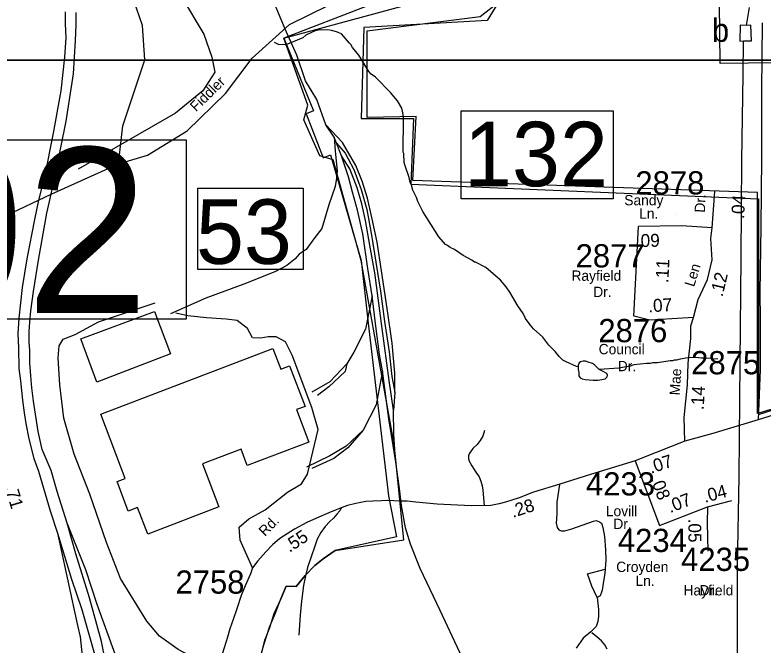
# Model space of a CAD drawing. Extents: x 1551653 to 1702041, y 811336 to 920032.
# Drawn here: x 1634040 to 1638801, y 827587 to 831594 of the extents above; entities that cross this region are included whole.
import ezdxf

# ---------------------------------------------------------------- set-up
doc = ezdxf.new("R2010")
doc.units = 0
for name, color, linetype in [('Old_Level_11', 7, 'Continuous'), ('Old_Level_17', 7, 'Continuous'), ('Old_Level_21', 7, 'Continuous'), ('Old_Level_22', 7, 'Continuous'), ('Old_Level_28', 7, 'Continuous'), ('Old_Level_31', 7, 'Continuous'), ('Old_Level_32', 7, 'Continuous'), ('Old_Level_35', 7, 'Continuous'), ('Old_Level_4', 7, 'Continuous'), ('Old_Level_41', 7, 'Continuous'), ('Old_Level_44', 7, 'Continuous'), ('Old_Level_47', 7, 'Continuous'), ('Old_Level_48', 7, 'Continuous'), ('Old_Level_49', 7, 'Continuous'), ('Old_Level_50', 7, 'Continuous'), ('Old_Level_56', 7, 'Continuous'), ('Old_Level_59', 7, 'Continuous'), ('Old_Level_62', 7, 'Continuous'), ('Old_Level_63', 7, 'Continuous'), ('Old_Level_8', 7, 'Continuous')]:
    doc.layers.add(name, color=color, linetype=linetype)

msp = doc.modelspace()

# ---------------------------------------------------------------- linework, layer by layer
at = {"layer": 'Old_Level_11'}
msp.add_line((1638247.283, 830327.148), (1638247.283, 830327.148), dxfattribs=at)
at = {"layer": 'Old_Level_28'}
for points in [[(1634358.924, 831613.638), (1634358.924, 831537.56), (1634362.23, 831448.913), (1634355.618, 831326.526), (1634332.478, 831111.522), (1634282.892, 830843.596), (1634226.694, 830565.745), (1634189.157, 830416.652)], [(1634270.63, 830455.02), (1634299.421, 830595.515), (1634365.535, 830919.673), (1634411.816, 831220.678), (1634425.039, 831431.712), (1634428.344, 831530.944), (1634428.344, 831610.33)], [(1634371.026, 828362.934), (1634308.827, 828564.219), (1634269.435, 828697.027), (1634213.472, 828829.841), (1634187.026, 828945.611), (1634173.802, 829028.306), (1634157.274, 829137.46), (1634147.356, 829223.463), (1634140.745, 829299.54), (1634134.134, 829382.234), (1634134.134, 829461.62), (1634130.828, 829511.236), (1634130.828, 829580.699), (1634134.134, 829640.238), (1634140.745, 829713.009), (1634157.274, 829835.395), (1634190.331, 830033.86), (1634243.223, 830334.203), (1634270.63, 830455.02)], [(1634189.157, 830416.652), (1634163.885, 830294.51), (1634114.3, 830043.783), (1634084.547, 829861.857), (1634074.63, 829762.625), (1634064.713, 829666.7), (1634058.101, 829567.468), (1634061.408, 829478.159), (1634064.713, 829345.849), (1634074.63, 829266.464), (1634087.854, 829144.077), (1634097.771, 829064.691), (1634107.688, 828995.228), (1634127.522, 828899.304), (1634160.58, 828773.61), (1634188.576, 828692.876), (1634263.214, 828439.713), (1634310.845, 828297.386)], [(1634706.713, 826688.852), (1634694.274, 826919.189), (1634679.155, 827039.961), (1634668.53, 827132.105), (1634667.321, 827172.353), (1634659.028, 827242.906), (1634646.588, 827325.911), (1634590.74, 827608.448), (1634514.028, 827886.513), (1634426.59, 828167.654), (1634371.026, 828362.934)], [(1634310.845, 828297.386), (1634400.052, 828006.014), (1634464.324, 827813.028), (1634549.274, 827512.993), (1634590.608, 827263.658), (1634591.389, 827220.176), (1634605.557, 827128.032), (1634626.315, 826932.859), (1634628.565, 826826.957), (1634634.148, 826751.105)]]:
    msp.add_lwpolyline(points, dxfattribs=at)
at = {"layer": 'Old_Level_31'}
for p, q in [((1634270.63, 830455.02), (1634270.63, 830455.02)), ((1634189.157, 830416.652), (1634189.157, 830416.652)), ((1636513.137, 828501.068), (1636513.137, 828501.068))]:
    msp.add_line(p, q, dxfattribs=at)
for points in [[(1636878.657, 830984.868), (1637847.179, 830984.868), (1637847.179, 830424.869), (1636878.657, 830424.869), (1636878.657, 830984.868)], [(1635202.761, 830493.353), (1635872.772, 830493.353), (1635872.772, 829975.07), (1635202.761, 829975.07), (1635202.761, 830493.353)]]:
    msp.add_lwpolyline(points, dxfattribs=at)
at = {"layer": 'Old_Level_32'}
for p, q in [((1638475.955, 830239.921), (1638492.8, 830471.752)), ((1637978.998, 829679.311), (1638008.478, 830248.351)), ((1637986.236, 828758.346), (1638141.372, 828347.597)), ((1638447.16, 828465.178), (1638601.884, 828506.66)), ((1638141.372, 828347.597), (1638447.16, 828465.178))]:
    msp.add_line(p, q, dxfattribs=at)
for points in [[(1638475.955, 830239.921), (1638282.226, 830252.566), (1638008.478, 830248.351)], [(1638358.033, 829670.881), (1638387.514, 829784.689), (1638446.474, 829911.142), (1638475.955, 830037.595), (1638467.531, 830172.479), (1638475.955, 830239.921)], [(1638358.033, 829670.881), (1638219.053, 829662.45), (1638080.074, 829654.02), (1637978.998, 829679.311)], [(1638303.283, 828882.655), (1638299.072, 829034.399), (1638320.129, 829240.94), (1638324.341, 829380.038), (1638341.187, 829535.997), (1638341.187, 829616.084), (1638358.033, 829670.881)], [(1639243.267, 829151.164), (1639189.106, 829142.423), (1639129.704, 829131.933), (1638770.493, 829020.049), (1638481.315, 828932.521), (1638303.283, 828882.655)], [(1638303.283, 828882.655), (1638119.613, 828810.373), (1637986.236, 828758.346)], [(1637986.236, 828758.346), (1637701.396, 828672.39), (1637506.982, 828609.054), (1637340.407, 828558.955), (1637247.5, 828523.201), (1637200.827, 828508.546), (1637162.338, 828496.442), (1637120.647, 828483.87), (1637068.833, 828474.931), (1636943.766, 828473.143), (1636727.579, 828482.082), (1636590.006, 828496.384), (1636535.101, 828500.83), (1636498.022, 828500.83), (1636491.172, 828501.308)], [(1636491.172, 828501.308), (1636409.443, 828507.014), (1636372.363, 828504.953), (1636316.744, 828502.891), (1636273.486, 828498.768), (1636209.627, 828486.401), (1636156.067, 828474.034), (1636114.868, 828459.606), (1636083.968, 828447.238), (1636036.589, 828426.626), (1635958.311, 828393.646), (1635896.511, 828366.851), (1635818.233, 828323.565), (1635772.913, 828294.709), (1635725.534, 828263.79), (1635678.155, 828224.627), (1635636.956, 828179.28), (1635584.185, 828121.586), (1635551.485, 828078.226), (1635538.802, 828039.177), (1635504.103, 827963.625), (1635478.322, 827902.246), (1635450.57, 827817.808), (1635427.675, 827749.83), (1635408.019, 827689.926), (1635393.105, 827637.5), (1635360.983, 827535.091)], [(1638447.16, 828465.178), (1638444.847, 828361.169), (1638446.104, 828275.299), (1638448.636, 828183.196)]]:
    msp.add_lwpolyline(points, dxfattribs=at)
at = {"layer": 'Old_Level_35'}
for points in [[(1635099.918, 831711.725), (1635241.901, 831471.781), (1635291.453, 831326.319), (1635311.275, 831230.447), (1635235.293, 831111.432), (1635060.364, 830970.191), (1634442.599, 830613.147)], [(1638794.954, 831543.394), (1638791.46, 831116.835), (1638789.713, 830685.03), (1638786.218, 830248.331), (1638780.977, 829832.261), (1638782.724, 829654.643), (1638782.724, 829339.968), (1638770.493, 829020.049)], [(1635328.24, 827429.008), (1635222.737, 827481.324), (1635077.381, 827557.361), (1634958.453, 827643.316), (1634879.168, 827739.188), (1634710.686, 828010.277), (1634621.49, 828238.387), (1634515.776, 828545.842), (1634416.669, 828800.4), (1634350.635, 829030.78), (1634324.207, 829242.361), (1634314.297, 829414.271), (1634320.903, 829490.308), (1634347.332, 829533.286), (1634423.314, 829563.039), (1634571.773, 829641.668), (1634931.861, 829763.988)], [(1635551.485, 828078.226), (1635472.731, 828254.063), (1635466.123, 828336.712), (1635528.892, 828389.608), (1635631.301, 828445.809), (1635773.355, 828558.211), (1635862.551, 828611.107), (1635902.193, 828673.92), (1635935.228, 828816.076), (1635968.264, 828958.232), (1635928.622, 829097.082), (1635803.086, 829430.984), (1635760.336, 829515.06), (1635700.872, 829548.119), (1635651.319, 829548.119), (1635605.069, 829538.201), (1635552.212, 829541.507), (1635519.177, 829601.014), (1635453.106, 829650.604), (1635383.731, 829660.522), (1635258.196, 829667.134), (1635139.268, 829680.357), (1635063.286, 829696.887)], [(1637027.894, 828952.057), (1637017.36, 828916.049), (1637000.788, 828888.372), (1636980.457, 828862.772), (1636954.122, 828837.093), (1636937.671, 828815.413), (1636929.627, 828803.573), (1636925.342, 828789.652), (1636927.058, 828775.61), (1636928.935, 828759.563), (1636946.287, 828727.191), (1636973.682, 828686.814), (1636993.078, 828656.604), (1637004.709, 828628.353), (1637012.343, 828600.184), (1637017.773, 828572.057), (1637025.597, 828474.313)], [(1637504.919, 828608.382), (1637487.274, 828495.385), (1637487.274, 828419.51), (1637483.827, 828360.879), (1637490.721, 828333.289), (1637501.061, 828319.493), (1637514.848, 828312.595), (1637538.976, 828312.595), (1637583.784, 828326.391), (1637721.655, 828374.675), (1637738.889, 828378.124), (1637759.569, 828371.226), (1637773.357, 828360.879), (1637780.25, 828333.289), (1637790.591, 828278.107), (1637797.484, 828191.885), (1637800.931, 828126.356), (1637794.038, 828043.583), (1637783.698, 827978.055), (1637776.804, 827936.668), (1637769.91, 827915.975), (1637763.017, 827898.731), (1637745.783, 827888.384)], [(1636114.868, 828459.606), (1636106.628, 828440.643), (1636088.088, 828420.031), (1636067.489, 828393.235), (1636042.992, 828371.743), (1636014.537, 828340.302), (1635986.768, 828303.045), (1635963.261, 828259.099), (1635948.563, 828215.175), (1635902.395, 828080.041), (1635889.494, 828026.271), (1635876.433, 827964.506), (1635864.009, 827865.103), (1635855.413, 827776.829), (1635845.41, 827648.965)], [(1637745.783, 827888.384), (1637711.315, 827960.81), (1637683.74, 828040.134), (1637796.251, 828070.155)], [(1637745.783, 827888.384), (1637752.676, 827812.509), (1637752.676, 827767.674), (1637749.229, 827736.634), (1637738.889, 827705.594), (1637704.421, 827671.105)], [(1637704.421, 827671.105), (1637656.167, 827629.719), (1637611.358, 827567.639)], [(1637807.825, 827560.741), (1637794.038, 827588.332), (1637773.357, 827612.474), (1637745.783, 827636.617), (1637711.315, 827664.208)]]:
    msp.add_lwpolyline(points, dxfattribs=at)
at = {"layer": 'Old_Level_4'}
msp.add_lwpolyline([(1631997.722, 830799.374), (1635129.916, 830799.374), (1635129.916, 829659.611), (1631997.722, 829659.611), (1631997.722, 830799.374)], dxfattribs=at)
at = {"layer": 'Old_Level_41'}
for points in [[(1634458.377, 829534.774), (1634926.552, 829707.698), (1635029.662, 829439.944), (1634561.487, 829258.654), (1634458.377, 829534.774)], [(1634586.013, 829054.492), (1635681.683, 829472.486), (1635731.741, 829341.274), (1635787.518, 829362.554), (1635885.908, 829104.657), (1635832.111, 829084.133), (1635910.844, 828877.762), (1635518.277, 828727.994), (1635478.176, 828833.105), (1635233.224, 828739.652), (1635337.834, 828465.459), (1634884.451, 828292.485), (1634820.321, 828460.577), (1634761.039, 828437.96), (1634688.925, 828626.977), (1634741.472, 828647.024), (1634586.013, 829054.492)]]:
    msp.add_lwpolyline(points, dxfattribs=at)
at = {"layer": 'Old_Level_44'}
for p, q in [((1636071.64, 830816.272), (1636017.228, 830895.735)), ((1636085.311, 830779.976), (1636071.64, 830816.272)), ((1636118.093, 830699.468), (1636085.311, 830779.976)), ((1636456.685, 829192.984), (1636449.208, 829081.075))]:
    msp.add_line(p, q, dxfattribs=at)
for points in [[(1636017.228, 830895.735), (1635961.26, 831056.358), (1635889.071, 831175.905), (1635832.911, 831337.897), (1635758.747, 831504.428), (1635669.669, 831719.552), (1635631.472, 831855.401), (1635602.436, 831936.501), (1635589.457, 832016.606), (1635575.311, 832139.713), (1635578.614, 832275.257), (1635596.03, 832374.566), (1635619.105, 832466.347), (1635652.671, 832581.928), (1635710.043, 832697.226), (1635775.249, 832794.352), (1635934.068, 832983.007)], [(1636456.685, 829192.984), (1636458.165, 829315.018), (1636440.658, 829507.278), (1636407.515, 829727.668), (1636372.538, 829966.106), (1636345.028, 830148.563), (1636311.026, 830306.939), (1636282.496, 830429.383), (1636250.084, 830537.9), (1636209.671, 830636.774), (1636123.205, 830783.608), (1636017.228, 830895.735)], [(1636071.64, 830816.272), (1636076.495, 830730.127), (1636090.902, 830601.968), (1636086.961, 830555.823), (1636077.703, 830503.983), (1636038.097, 830386.522), (1635991.585, 830235.758), (1635940.833, 830169.821), (1635892.478, 830103.52), (1635848.309, 830072.082), (1635823.104, 830044.012), (1635770.247, 830001.035), (1635694.265, 829961.364), (1635496.052, 829882.021), (1635254.893, 829792.76), (1635030.251, 829693.581)], [(1636085.311, 830779.976), (1636140.426, 830715.222), (1636196.541, 830611.026), (1636243.385, 830484.009), (1636279.635, 830357.405), (1636309.513, 830193.107), (1636337.269, 830022.655), (1636366.938, 829838.151), (1636390.406, 829643.971), (1636421.915, 829451.429), (1636437.951, 829295.219), (1636456.685, 829192.984)], [(1636449.208, 829081.075), (1636421.616, 829269.336), (1636375.908, 829600.041), (1636330.484, 829954.755), (1636298.851, 830131.093), (1636270.813, 830287.546), (1636246.157, 830393.904), (1636217.381, 830494.34), (1636169.842, 830616.771), (1636118.093, 830699.468)], [(1636312.512, 829808.843), (1636284.799, 829981.297), (1636253.657, 830201.647), (1636219.697, 830352.218), (1636187.201, 830466.538), (1636162.384, 830564.894), (1636118.093, 830699.468)], [(1636312.512, 829808.843), (1636269.991, 829596.504), (1636195.167, 829448.77), (1636150.678, 829375.915)], [(1636379.138, 829330.288), (1636359.733, 829434.28), (1636336.183, 829614.657), (1636312.512, 829808.843)], [(1636150.678, 829375.915), (1636043.499, 829260.561), (1635928.231, 829195.8)], [(1636150.678, 829375.915), (1636140.567, 829327.344), (1636037.432, 829228.18), (1635964.632, 829173.539)], [(1636379.138, 829330.288), (1636338.693, 829113.747), (1636255.781, 828953.87)], [(1636460.996, 828764.865), (1636418.463, 829025.468), (1636379.138, 829330.288)], [(1636460.996, 828764.865), (1636451.121, 828928.953), (1636449.208, 829081.075)], [(1636255.781, 828953.87), (1636146.58, 828852.683), (1636043.445, 828789.946), (1635895.822, 828717.091)], [(1636255.781, 828953.87), (1636158.713, 828840.539), (1636069.734, 828773.756), (1635928.178, 828708.996)], [(1638019.989, 825168.081), (1637879.802, 825458.084), (1637690.957, 825864.536), (1637538.927, 826162.584), (1637443.563, 826363.827), (1637373.465, 826498.722), (1637200.05, 826857.034), (1637087.048, 827086.453), (1636991.763, 827291.699), (1636871.126, 827539.28), (1636744.696, 827806.99), (1636618.023, 828072.705), (1636556.134, 828227.445), (1636525.438, 828331.923), (1636499.316, 828474.331), (1636486.705, 828582.444), (1636460.996, 828764.865)]]:
    msp.add_lwpolyline(points, dxfattribs=at)
at = {"layer": 'Old_Level_47'}
for points in [[(1634914.952, 826501.495), (1634927.338, 826559.336), (1634936.85, 826651.499), (1634932.07, 826716.054), (1634928.579, 826785.921), (1634924.409, 826821.659), (1634903.676, 826908.813), (1634847.698, 827047.846), (1634737.813, 827359.113), (1634561.769, 827844.155), (1634491.277, 828064.117), (1634371.026, 828362.934)], [(1634310.845, 828297.386), (1634419.707, 827790.468), (1634439.453, 827702.969), (1634453.557, 827638.052), (1634462.019, 827559.02), (1634470.482, 827477.168), (1634467.662, 827375.557), (1634456.378, 827268.301), (1634442.274, 827189.27), (1634428.17, 827121.529), (1634405.604, 827048.144), (1634385.858, 826977.581)]]:
    msp.add_lwpolyline(points, dxfattribs=at)
at = {"layer": 'Old_Level_48'}
for points in [[(1635588.429, 827466.777), (1635624.173, 827587.636), (1635660.185, 827700.934), (1635699.992, 827794.925), (1635731.391, 827881.366), (1635766.043, 827961.803), (1635828.768, 827959.655), (1635885.625, 828028.536), (1635947.781, 828091.893), (1636001.521, 828135.78), (1636078.128, 828188.649), (1636513.644, 828256.76), (1636458.499, 828805.521), (1636452.633, 828865.255), (1636243.871, 830033.203), (1636065.099, 830672.246), (1635979.97, 830697.808), (1635877.815, 830927.863), (1635903.354, 831021.59), (1635750.121, 831447.618), (1636941.932, 831771.4)], [(1637112.191, 831669.153), (1637044.088, 831558.386), (1636260.897, 831515.783), (1636243.871, 830936.384), (1636575.876, 830936.384), (1636558.85, 830518.876)], [(1638522.965, 831669.337), (1638883.439, 831673.788), (1638887.89, 831290.974), (1638527.416, 831286.523), (1638522.965, 831669.337)], [(1636558.85, 830518.876), (1638772.213, 830425.149), (1638772.213, 829053.337), (1639087.192, 829155.584)]]:
    msp.add_lwpolyline(points, dxfattribs=at)
at = {"layer": 'Old_Level_49'}
for points in [[(1636572.248, 830542.241), (1636592.241, 830949.27), (1636280.254, 830942.503), (1636280.767, 831493.683), (1637000.089, 831585.136), (1637125.171, 831682.638)], [(1636279.536, 831651.06), (1635750.121, 831447.618), (1635940.483, 830984.128), (1635893.833, 830966.186), (1636000.973, 830685.932), (1636047.725, 830703.874), (1636243.871, 830033.203), (1636288.483, 829633.23), (1636416.511, 828536.012), (1636467.467, 828274.263), (1636078.128, 828188.649), (1636001.521, 828135.78), (1635947.781, 828091.893), (1635885.625, 828028.536), (1635828.768, 827959.655), (1635766.043, 827961.803), (1635731.391, 827881.366), (1635687.126, 827784.13), (1635659.528, 827695.846), (1635628.01, 827615.588), (1635588.429, 827466.777)], [(1639087.192, 829155.584), (1638764.973, 829060.33), (1638764.255, 830464.476), (1636572.248, 830542.241)]]:
    msp.add_lwpolyline(points, dxfattribs=at)
at = {"layer": 'Old_Level_50'}
for p, q in [((1634216.657, 830423.245), (1634216.657, 830423.245)), ((1636489.498, 828504.21), (1636489.498, 828504.21))]:
    msp.add_line(p, q, dxfattribs=at)
at = {"layer": 'Old_Level_56'}
msp.add_line((1638695.86, 831526.973), (1638715.417, 831642.638), dxfattribs=at)
for points in [[(1638695.86, 831526.973), (1638655.887, 831529.387), (1638652.616, 831427.396), (1638676.661, 831429.109)], [(1638676.661, 831429.109), (1638726.716, 831430.493), (1638723.908, 831528.603), (1638695.86, 831526.973)], [(1638613.416, 825833.588), (1638616.369, 826067.656), (1638618.396, 826689.548), (1638637.999, 827457.361), (1638638.072, 828081.497), (1638649.41, 828659.377), (1638654.512, 829383.263), (1638661.037, 830049.285), (1638665.03, 830669.34), (1638673.879, 831213.249), (1638676.661, 831429.109)]]:
    msp.add_lwpolyline(points, dxfattribs=at)
at = {"layer": 'Old_Level_59'}
for points in [[(1634698.892, 830646.972), (1634883.849, 830702.284), (1635134.833, 830858.021), (1635379.87, 831095.984), (1635549.858, 831319.081), (1635785.873, 831534.181), (1636036.857, 831657.109), (1636605.877, 831799.826), (1637731.92, 831911.579), (1639236.9, 832284.774), (1639446.976, 832365.821), (1639875.945, 832728.096), (1639977.958, 832883.578)], [(1634698.892, 830646.972), (1634726.882, 830889.292), (1634865.907, 831309.956), (1634851.861, 831526.85), (1634754.872, 831804.593), (1634735.904, 832320.35), (1634687.922, 832488.698)], [(1631311.239, 828442.267), (1631358.677, 828491.465), (1632279.79, 829058.074), (1632607.874, 829346.839), (1633204.883, 829797.492), (1633936.816, 830298.076), (1634189.157, 830416.652), (1634270.63, 830455.02), (1634698.892, 830646.972)]]:
    msp.add_lwpolyline(points, dxfattribs=at)
at = {"layer": 'Old_Level_62'}
for points in [[(1637624.268, 829357.04), (1637614.22, 829358.988), (1637548.501, 829387.49), (1637526.663, 829399.691), (1637502.775, 829421.837), (1637477.04, 829454.03), (1637437.363, 829494.322), (1637399.838, 829544.612), (1637340.271, 829599.053), (1637318.433, 829623.198), (1637288.7, 829663.388), (1637273.014, 829695.479), (1637239.385, 829743.717), (1637189.968, 829832.043), (1637166.284, 829866.236), (1637130.605, 829908.477), (1637035.256, 829989.216), (1636971.587, 830021.666), (1636963.59, 830021.768), (1636947.699, 830033.866), (1636891.924, 830064.316), (1636836.253, 830102.712), (1636808.366, 830114.913), (1636792.474, 830129.061), (1636780.581, 830135.11), (1636736.905, 830183.452), (1636636.224, 830344.161), (1636602.698, 830408.342), (1636594.804, 830432.436), (1636571.223, 830480.572), (1636563.431, 830512.611), (1636555.536, 830528.657), (1636547.744, 830560.696), (1636520.37, 830640.871), (1636516.474, 830656.865), (1636514.936, 830712.844), (1636510.938, 830720.893), (1636512.475, 830936.711), (1636510.63, 830960.702), (1636500.89, 831000.738), (1636473.311, 831048.925), (1636429.737, 831101.265), (1636334.49, 831197.947), (1636306.603, 831218.144), (1636290.814, 831234.241), (1636227.556, 831338.715), (1636187.981, 831386.953), (1636178.138, 831407.048), (1636168.193, 831415.097), (1636118.673, 831473.485), (1636086.787, 831487.736), (1636054.799, 831495.99), (1636030.911, 831500.142), (1635990.926, 831498.502), (1635982.928, 831500.552), (1635950.94, 831492.812), (1635926.847, 831483.02), (1635890.758, 831465.335), (1635870.662, 831449.494), (1635774.493, 831408.279), (1635758.499, 831404.434), (1635716.566, 831406.741), (1635690.729, 831419.556)], [(1637756.732, 829339.508), (1637741.66, 829356.322), (1637728.537, 829368.677), (1637714.286, 829377.7), (1637688.552, 829386.517), (1637670.507, 829392.309), (1637655.026, 829392.514), (1637639.852, 829388.26), (1637629.497, 829382.108), (1637624.063, 829364.832), (1637624.268, 829357.04)], [(1638513.681, 829407.74), (1638489.69, 829405.945), (1638473.799, 829410.046), (1638425.816, 829412.456), (1638409.822, 829410.559), (1638369.94, 829414.865), (1638321.958, 829413.276), (1638273.975, 829405.689), (1638249.882, 829397.845), (1638233.888, 829398), (1638225.891, 829394.052), (1638209.897, 829394.206), (1638129.926, 829380.826), (1638097.938, 829381.083), (1638081.944, 829377.238), (1638057.953, 829377.443), (1637977.983, 829368.062), (1637953.889, 829360.27), (1637881.916, 829346.839), (1637756.732, 829339.508)], [(1637624.268, 829357.04), (1637624.575, 829339.765), (1637627.241, 829320.541), (1637629.189, 829299.113), (1637636.776, 829286.451), (1637648.464, 829279.685), (1637668.764, 829275.737), (1637694.908, 829274.251), (1637720.027, 829270.611), (1637748.427, 829271.021), (1637773.546, 829275.122), (1637794.974, 829280.351), (1637807.687, 829292.346), (1637811.173, 829304.137), (1637805.739, 829314.543), (1637782.261, 829326.642), (1637756.732, 829339.508)]]:
    msp.add_lwpolyline(points, dxfattribs=at)
at = {"layer": 'Old_Level_63'}
for points in [[(1631612.821, 874749.337), (1694128.892, 874749.337), (1694128.892, 831307.151), (1631612.821, 831307.151), (1631612.821, 874749.337)], [(1577049.889, 831307.151), (1641328.558, 831307.151), (1641328.558, 811336.298), (1577049.889, 811336.298), (1577049.889, 831307.151)]]:
    msp.add_lwpolyline(points, dxfattribs=at)

# ---------------------------------------------------------------- texts
at = {"layer": 'Old_Level_11'}
for s, p in [('Sandy', (1637917.466, 830383.585)), ('Ln.', (1638012.295, 830298.698)), ('Rayfield', (1637581.264, 829903.486)), ('Dr.', (1637719.894, 829800.176)), ('Council', (1637754.514, 829436.238)), ('Dr.', (1637876.147, 829328.571)), ('Lovill', (1637800.184, 828406.172)), ('Dr.', (1637847.838, 828324.623)), ('Croyden', (1637866.325, 828051.265)), ('Ln.', (1637989.09, 827962.519)), ('Hayfield', (1638294.379, 827902.232)), ('Dr.', (1638396.684, 827902.232))]:
    msp.add_text(s, height=65.6167, dxfattribs=at).set_placement(p)
for s, rotation, p in [('Dr.', 86.890736, (1638429.98, 830335.758)), ('Len', 72.780372, (1638361.616, 829861.02)), ('Mae', 86.805517, (1638270.917, 829173.701)), ('Rd.', 45.513111, (1635630.61, 828274.511))]:
    msp.add_text(s, height=65.6167, rotation=rotation, dxfattribs=at).set_placement(p)
at = {"layer": 'Old_Level_17'}
for s, rotation, p in [('.04', 86.890736, (1638679.588, 830295.832)), ('.09', 0.882147, (1637991.528, 830118.062)), ('.11', 87.034361, (1638197.505, 829888.31)), ('.12', 76.572367, (1638542.305, 829797.872)), ('.07', 3.47115, (1638072.32, 829702.769)), ('.14', 86.805517, (1638422.681, 829080.379)), ('.07', 18.006547, (1638087.431, 828675.961)), ('.08', 290.646419, (1638082.627, 828643.783)), ('.71', 286.848725, (1633973.161, 828592.111)), ('.04', 15.008519, (1638430.521, 828490.66)), ('.07', 21.205808, (1638209.648, 828425.485)), ('.28', 18.138908, (1637208.419, 828395.012)), ('.05', 270.838372, (1638324.315, 828390.657)), ('.55', 33.329256, (1635786.546, 828172.635))]:
    msp.add_text(s, height=82.0208, rotation=rotation, dxfattribs=at).set_placement(p)
at = {"layer": 'Old_Level_21'}
msp.add_text('Fiddler', height=65.6167, rotation=44.450658, dxfattribs=at).set_placement((1635191.716, 830975.456))
at = {"layer": 'Old_Level_22'}
msp.add_text('b', height=147.637, dxfattribs=at).set_placement((1638474.915, 831423.499))
at = {"layer": 'Old_Level_31'}
for s, p in [('132', (1636898.023, 830504.987)), ('53', (1635191.601, 830011.32))]:
    msp.add_text(s, height=410.1042, dxfattribs=at).set_placement(p)
at = {"layer": 'Old_Level_4'}
msp.add_text('J592', height=1049.8646, dxfattribs=at).set_placement((1631845.798, 829699.682))
at = {"layer": 'Old_Level_8'}
for s, p in [('2878', (1637987.938, 830452.838)), ('2877', (1637607.5, 829988.792)), ('2876', (1637752.224, 829512.972)), ('2875', (1638342.867, 829308.738)), ('4233', (1637673.849, 828538.027)), ('4234', (1637876.43, 828178.322)), ('4235', (1638278.913, 828058.071)), ('2758', (1635061.185, 827913.365))]:
    msp.add_text(s, height=147.6375, dxfattribs=at).set_placement(p)

doc.saveas('drawing.dxf')
